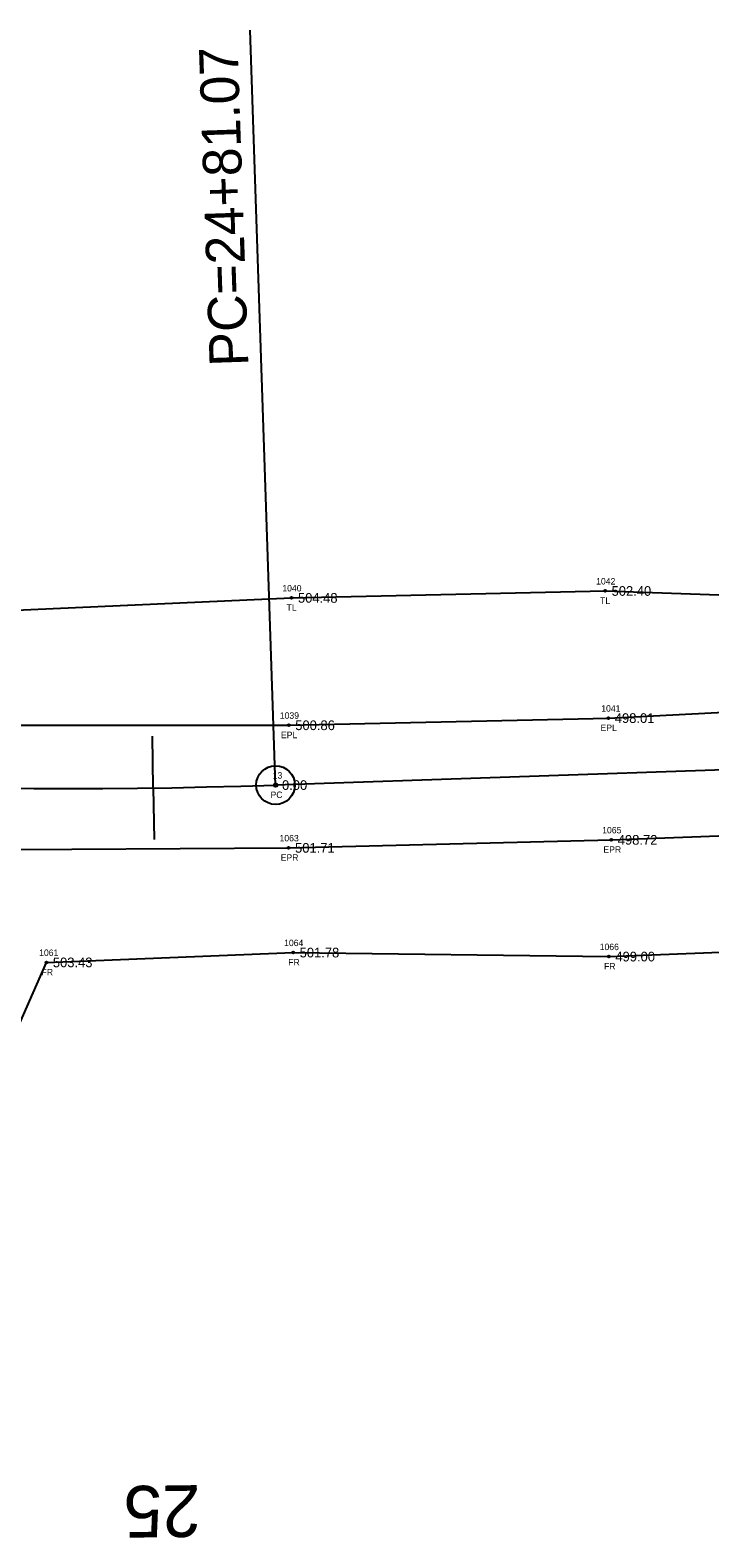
# Model space of a CAD drawing. Extents: x 1784103 to 1787401, y 770251 to 771298.
# Drawn here: x 1785241.1 to 1785346.4, y 770720.4 to 770953.8 of the extents above; entities that cross this region are included whole.
import ezdxf

# ---------------------------------------------------------------- set-up
doc = ezdxf.new("R2010")
doc.units = 0
for name, color, linetype in [('RD_EX_Fence_Other', 7, 'Continuous'), ('RD_EX_Fence_Other_txCode', 7, 'Continuous'), ('RD_EX_Road', 7, 'Continuous'), ('RD_EX_Road_txCode', 7, 'Continuous'), ('RD_EX_TX_Fence_Other_ELEV', 7, 'Continuous'), ('RD_EX_TX_Road_ELEV', 7, 'Continuous'), ('RD_EX_TX_VEG_ELEV', 7, 'Continuous'), ('RD_EX_VEG', 7, 'Continuous'), ('RD_EX_VEG_txCode', 7, 'Continuous'), ('RD_HC_Cl', 7, 'Continuous'), ('RD_HC_Data', 7, 'Continuous'), ('RD_HC_Data_Tic', 7, 'Continuous'), ('RD_HC_Survey_ELEV', 7, 'Continuous'), ('RD_HC_TX_Sta50', 7, 'Continuous'), ('RD_HC_txCode', 7, 'Continuous'), ('RD_SMD_Locator', 7, 'Continuous')]:
    doc.layers.add(name, color=color, linetype=linetype)

msp = doc.modelspace()

# ---------------------------------------------------------------- linework, layer by layer
at = {"layer": 'RD_EX_Fence_Other'}
msp.add_lwpolyline([(1785232.56, 770784.32), (1785243.65, 770809.45), (1785281.87, 770810.97), (1785330.77, 770810.35), (1785381.35, 770812.32), (1785481.48, 770815.35), (1785580.21, 770817.42), (1785680.43, 770820.14), (1785794.9, 770821.68), (1785847.9, 770822.69), (1785879.84, 770822.3), (1785979.43, 770826.69), (1786080.46, 770830.52), (1786182.98, 770833.3), (1786235.76, 770836.16), (1786247.48, 770836.31), (1786280.27, 770837.57), (1786379.57, 770841.87), (1786481.1, 770846.08), (1786539.49, 770848.17), (1786546.34, 770841.89)], dxfattribs=at)
at = {"layer": 'RD_EX_Road'}
for points in [[(1785083.87, 770860.72), (1785132.91, 770853.08), (1785181.89, 770848.53), (1785200.96, 770847.97), (1785215.21, 770848.13), (1785231.38, 770846.18), (1785281.19, 770846.16), (1785330.68, 770847.27), (1785380.41, 770849.82), (1785480.96, 770852.71), (1785580.09, 770856.45), (1785680.2, 770859.84), (1785779.71, 770863.4)], [(1785079.74, 770841.1), (1785077.36, 770829.81), (1785127.59, 770822.23), (1785177.27, 770813.99), (1785180.45, 770828), (1785230.74, 770826.87), (1785281.16, 770827.18), (1785331.14, 770828.42), (1785381.03, 770830.27), (1785481.34, 770833.99), (1785580.1, 770837.94), (1785680.6, 770840.57), (1785780.28, 770843.87)]]:
    msp.add_lwpolyline(points, dxfattribs=at)
at = {"layer": 'RD_EX_VEG'}
msp.add_lwpolyline([(1785221.61, 770869.17), (1785226.44, 770862.44), (1785230.83, 770863.64), (1785281.61, 770865.88), (1785330.18, 770866.95), (1785378.64, 770865.28), (1785481.03, 770871.22), (1785579.9, 770882.43), (1785678.49, 770873.66), (1785753.25, 770880.69), (1785777.57, 770887.66), (1785796.72, 770894.6), (1785878.49, 770883.8), (1786077.63, 770894.05), (1786177.75, 770898.7), (1786232.19, 770912.93), (1786276.99, 770915.77), (1786313.89, 770919.94), (1786357.9, 770947.77)], dxfattribs=at)
at = {"layer": 'RD_HC_Cl'}
msp.add_line((1787025.56, 770895.93), (1785279.14, 770836.9), dxfattribs=at)
msp.add_arc((1785246.88, 771791.29), 954.93, 251.4323, 271.9359, dxfattribs=at)
at = {"layer": 'RD_HC_Data'}
msp.add_line((1785279.14, 770836.9), (1785275.19, 770953.77), dxfattribs=at)
for radius in [3, 0.282]:
    msp.add_circle((1785279.14, 770836.9), radius, dxfattribs=at)
at = {"layer": 'RD_HC_Data_Tic'}
for q in [(1785260.1, 770844.45), (1785260.32, 770828.45)]:
    msp.add_line((1785260.21, 770836.45), q, dxfattribs=at)
at = {"layer": 'RD_SMD_Locator'}
for centre in [(1785281.61, 770865.88), (1785330.18, 770866.95), (1785330.68, 770847.27), (1785281.19, 770846.16), (1785279.14, 770836.9), (1785331.14, 770828.42), (1785281.16, 770827.18), (1785243.65, 770809.45), (1785281.87, 770810.97), (1785330.77, 770810.35)]:
    msp.add_circle(centre, 0.15, dxfattribs=at)

# ---------------------------------------------------------------- texts
at = {"layer": 'RD_EX_Fence_Other_txCode'}
for s, p in [('1064', (1785280.46, 770811.97)), ('1066', (1785329.34, 770811.35)), ('1061', (1785242.53, 770810.45)), ('FR', (1785281.11, 770808.97)), ('FR', (1785330.01, 770808.35)), ('FR', (1785242.9, 770807.45))]:
    msp.add_text(s, height=1, dxfattribs=at).set_placement(p)
at = {"layer": 'RD_EX_Road_txCode'}
for s, p in [('1041', (1785329.58, 770848.27)), ('1039', (1785279.8, 770847.16)), ('EPL', (1785279.98, 770844.16)), ('EPL', (1785329.47, 770845.27)), ('1065', (1785329.73, 770829.42)), ('1063', (1785279.76, 770828.18)), ('EPR', (1785279.94, 770825.18)), ('EPR', (1785329.92, 770826.42))]:
    msp.add_text(s, height=1, dxfattribs=at).set_placement(p)
at = {"layer": 'RD_EX_TX_Fence_Other_ELEV'}
for s, p in [('501.78', (1785282.87, 770810.22)), ('503.43', (1785244.65, 770808.7)), ('499.00', (1785331.77, 770809.6))]:
    msp.add_text(s, height=1.5, dxfattribs=at).set_placement(p)
at = {"layer": 'RD_EX_TX_Road_ELEV'}
for s, p in [('500.86', (1785282.19, 770845.41)), ('498.01', (1785331.68, 770846.52)), ('501.71', (1785282.16, 770826.43)), ('498.72', (1785332.14, 770827.67))]:
    msp.add_text(s, height=1.5, dxfattribs=at).set_placement(p)
at = {"layer": 'RD_EX_TX_VEG_ELEV'}
for s, p in [('502.40', (1785331.18, 770866.2)), ('504.48', (1785282.61, 770865.13))]:
    msp.add_text(s, height=1.5, dxfattribs=at).set_placement(p)
at = {"layer": 'RD_EX_VEG_txCode'}
for s, p in [('1040', (1785280.19, 770866.88)), ('1042', (1785328.79, 770867.95)), ('TL', (1785329.4, 770864.95)), ('TL', (1785280.84, 770863.88))]:
    msp.add_text(s, height=1, dxfattribs=at).set_placement(p)
at = {"layer": 'RD_HC_Data'}
msp.add_text('PC=24+81.07', height=6, rotation=91.9359, dxfattribs=at).set_placement((1785274.94, 770901.8))
at = {"layer": 'RD_HC_Survey_ELEV'}
msp.add_text('0.00', height=1.5, dxfattribs=at).set_placement((1785280.14, 770836.15))
at = {"layer": 'RD_HC_TX_Sta50'}
msp.add_text('25', height=8, rotation=180.7999, dxfattribs=at).set_placement((1785267.48, 770728.54))
at = {"layer": 'RD_HC_txCode'}
for s, p in [('13', (1785278.69, 770837.9)), ('PC', (1785278.36, 770834.9))]:
    msp.add_text(s, height=1, dxfattribs=at).set_placement(p)

doc.saveas('drawing.dxf')
